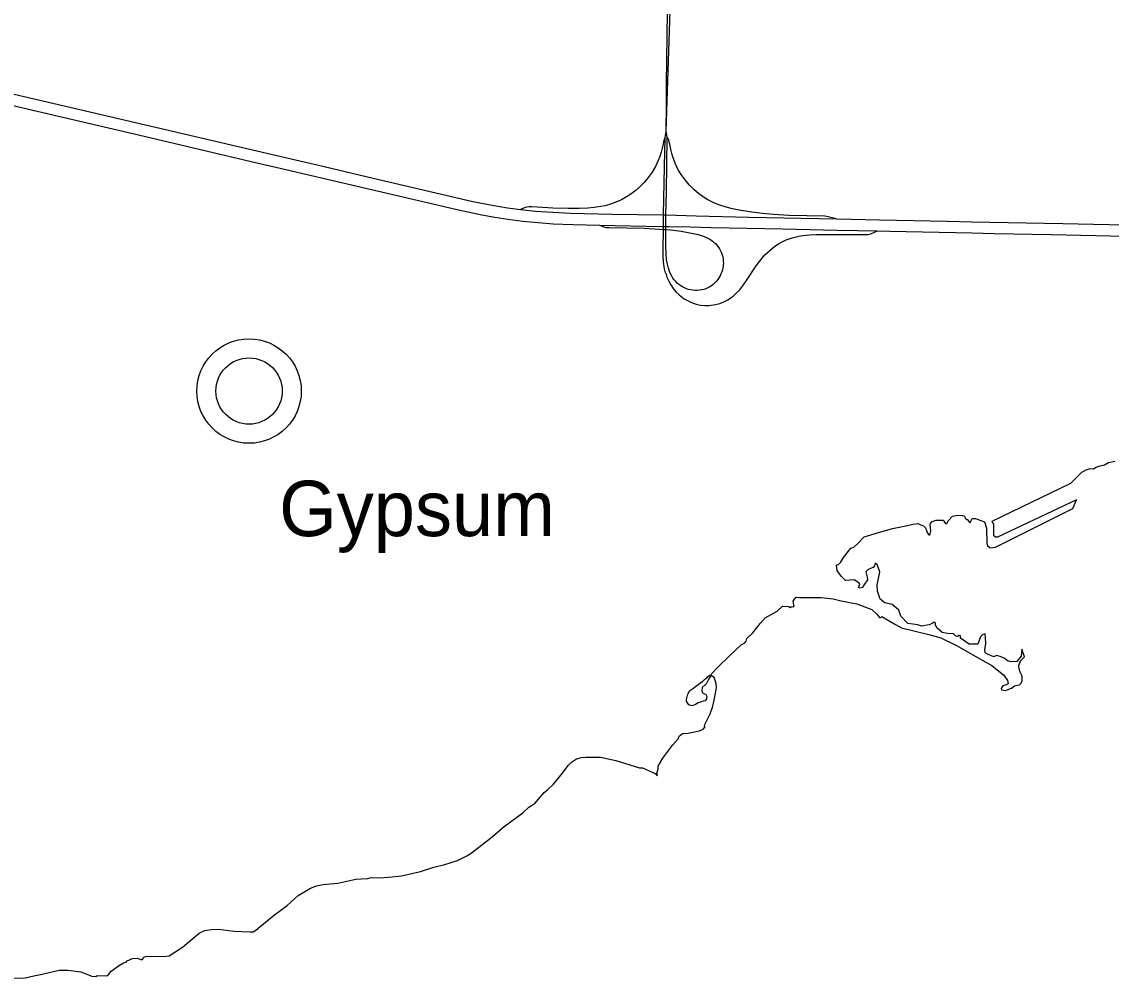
# Model space of a CAD drawing. Extents: x -82 to 873, y 0 to 440.
# Drawn here: x 461.25 to 481.74, y 152.95 to 170.93 of the extents above; entities that cross this region are included whole.
import ezdxf

# ---------------------------------------------------------------- set-up
doc = ezdxf.new("R2010")
doc.units = 0
for name, color, linetype in [('DV_X_Corp_Line', 7, 'Continuous'), ('GM_P_US_Alignment', 7, 'Continuous'), ('GM_X_County', 7, 'Continuous'), ('GM_X_Interchange_Ramps', 7, 'Continuous'), ('GM_X_Interstate_Route', 7, 'Continuous')]:
    doc.layers.add(name, color=color, linetype=linetype)

msp = doc.modelspace()

# ---------------------------------------------------------------- linework, layer by layer
at = {"layer": 'DV_X_Corp_Line'}
for radius in [0.982, 0.623]:
    msp.add_circle((465.521, 163.993), radius, dxfattribs=at)
at = {"layer": 'GM_P_US_Alignment'}
msp.add_lwpolyline([(473.365, 168.87), (473.535, 173.991), (473.96, 183.618), (473.906, 187.531), (484.23, 206.176), (490.737, 211.48), (492.433, 215.185), (491.986, 239.02), (491.811, 239.475), (491.569, 239.636), (491.322, 239.672), (489.332, 239.581), (489.281, 240.625)], dxfattribs=at)
at = {"layer": 'GM_X_County'}
msp.add_lwpolyline([(461, 152.955), (461.307, 152.964), (461.475, 152.998), (461.627, 153.029), (461.95, 153.107), (462.112, 153.108), (462.355, 153.077), (462.56, 152.994), (462.635, 152.99), (462.665, 153.004), (462.848, 153.002), (462.885, 153.03), (462.924, 153.089), (463.082, 153.2), (463.159, 153.245), (463.206, 153.258), (463.228, 153.282), (463.325, 153.326), (463.417, 153.333), (463.48, 153.306), (463.516, 153.309), (463.529, 153.324), (463.537, 153.348), (463.605, 153.372), (463.918, 153.365), (464.019, 153.375), (464.271, 153.537), (464.58, 153.801), (464.686, 153.849), (464.806, 153.868), (464.95, 153.874), (465.231, 153.842), (465.538, 153.824), (465.596, 153.824), (465.645, 153.857), (465.728, 153.925), (465.999, 154.149), (466.237, 154.324), (466.443, 154.507), (466.674, 154.646), (466.79, 154.692), (466.917, 154.714), (467.192, 154.739), (467.528, 154.814), (467.637, 154.824), (467.754, 154.827), (467.816, 154.846), (467.98, 154.842), (468.212, 154.863), (468.39, 154.879), (468.744, 154.958), (468.994, 155.042), (469.204, 155.094), (469.442, 155.166), (469.616, 155.256), (469.698, 155.308), (470.06, 155.589), (470.319, 155.808), (470.669, 156.066), (470.781, 156.17), (470.833, 156.201), (470.886, 156.231), (471.07, 156.445), (471.143, 156.504), (471.244, 156.6), (471.413, 156.812), (471.523, 156.956), (471.584, 157.014), (471.679, 157.077), (471.774, 157.102), (471.855, 157.111), (472.129, 157.11), (472.277, 157.081), (472.418, 157.046), (472.864, 156.911), (472.919, 156.908), (473.158, 156.805), (473.192, 156.768), (473.204, 156.772), (473.188, 156.81), (473.214, 156.885), (473.215, 156.942), (473.306, 157.089), (473.493, 157.345), (473.594, 157.452), (473.61, 157.506), (473.671, 157.555), (473.777, 157.563), (473.992, 157.608), (474.064, 157.638), (474.098, 157.679), (474.087, 157.7), (474.092, 157.727), (474.187, 157.914), (474.235, 158.044), (474.269, 158.183), (474.312, 158.413), (474.308, 158.497), (474.266, 158.609), (474.219, 158.64), (474.196, 158.622), (474.179, 158.603), (474.156, 158.557), (474.122, 158.496), (474.104, 158.475), (474.044, 158.419), (474.034, 158.356), (474.044, 158.328), (474.087, 158.302), (474.114, 158.291), (474.13, 158.253), (474.123, 158.205), (474.099, 158.167), (474.059, 158.165), (474.03, 158.149), (473.97, 158.132), (473.918, 158.1), (473.854, 158.075), (473.794, 158.091), (473.767, 158.13), (473.75, 158.165), (473.745, 158.193), (473.774, 158.292), (473.812, 158.365), (473.859, 158.398), (473.996, 158.501), (474.052, 158.533), (474.09, 158.579), (474.129, 158.599), (474.144, 158.622), (474.19, 158.653), (474.212, 158.661), (474.223, 158.683), (474.33, 158.794), (474.554, 159.015), (474.783, 159.226), (474.837, 159.251), (474.871, 159.289), (474.884, 159.342), (474.995, 159.447), (475.133, 159.626), (475.229, 159.732), (475.453, 159.857), (475.551, 159.949), (475.673, 159.945), (475.696, 159.926), (475.714, 159.936), (475.735, 159.945), (475.757, 159.935), (475.774, 159.948), (475.766, 159.969), (475.753, 160.041), (475.778, 160.081), (475.813, 160.117), (475.872, 160.109), (475.998, 160.109), (476.279, 160.109), (476.506, 160.086), (476.655, 160.049), (476.949, 159.993), (477.234, 159.886), (477.327, 159.797), (477.376, 159.738), (477.406, 159.739), (477.425, 159.755), (477.527, 159.694), (477.681, 159.606), (477.789, 159.541), (478.306, 159.415), (478.529, 159.355), (478.824, 159.209), (479.104, 159.051), (479.267, 158.958), (479.491, 158.832), (479.72, 158.65), (479.785, 158.552), (479.799, 158.487), (479.762, 158.468), (479.697, 158.454), (479.669, 158.403), (479.673, 158.375), (479.748, 158.361), (479.86, 158.407), (479.92, 158.449), (480.014, 158.468), (480.044, 158.5), (480.06, 158.543), (480.06, 158.636), (480.023, 158.71), (480.003, 158.771), (480, 158.832), (480.039, 158.928), (480.105, 158.994), (480.056, 159.14), (480.046, 159.009), (479.962, 158.911), (479.855, 158.902), (479.786, 158.924), (479.734, 158.967), (479.645, 159), (479.58, 159.024), (479.529, 158.995), (479.407, 159.046), (479.365, 159.074), (479.361, 159.13), (479.379, 159.247), (479.375, 159.354), (479.364, 159.427), (479.323, 159.415), (479.281, 159.373), (479.23, 159.233), (479.141, 159.237), (479.062, 159.237), (478.904, 159.345), (478.899, 159.391), (478.879, 159.398), (478.848, 159.377), (478.808, 159.393), (478.773, 159.429), (478.656, 159.433), (478.554, 159.452), (478.46, 159.536), (478.43, 159.591), (478.429, 159.635), (478.405, 159.65), (478.372, 159.626), (478.311, 159.601), (478.171, 159.573), (478.101, 159.601), (477.91, 159.62), (477.779, 159.76), (477.742, 159.872), (477.691, 159.918), (477.615, 159.981), (477.476, 160.012), (477.392, 160.082), (477.341, 160.231), (477.336, 160.343), (477.383, 160.595), (477.336, 160.73), (477.299, 160.758), (477.285, 160.707), (477.257, 160.674), (477.21, 160.655), (477.168, 160.637), (477.122, 160.595), (477.145, 160.497), (477.154, 160.441), (477.084, 160.343), (477.056, 160.297), (477.017, 160.289), (476.986, 160.298), (477.01, 160.361), (476.991, 160.389), (476.902, 160.441), (476.739, 160.431), (476.66, 160.511), (476.581, 160.618), (476.567, 160.725), (476.604, 160.734), (476.646, 160.772), (476.702, 160.865), (476.842, 161.042), (476.893, 161.056), (476.968, 161.126), (477.092, 161.25), (477.343, 161.326), (477.623, 161.411), (477.904, 161.466), (478.003, 161.49), (478.108, 161.504), (478.152, 161.477), (478.174, 161.473), (478.209, 161.459), (478.242, 161.423), (478.281, 161.323), (478.306, 161.289), (478.325, 161.287), (478.334, 161.306), (478.341, 161.361), (478.331, 161.492), (478.371, 161.543), (478.445, 161.565), (478.581, 161.567), (478.589, 161.548), (478.611, 161.509), (478.628, 161.499), (478.653, 161.514), (478.675, 161.559), (478.75, 161.639), (478.854, 161.662), (478.937, 161.652), (478.968, 161.643), (478.981, 161.629), (478.992, 161.601), (479.028, 161.58), (479.064, 161.532), (479.082, 161.515), (479.099, 161.547), (479.123, 161.598), (479.182, 161.598), (479.214, 161.587), (479.351, 161.537), (479.392, 161.414), (479.394, 161.135), (479.412, 161.087), (479.46, 161.045), (479.563, 161.057), (481.014, 161.786), (481.086, 161.948), (479.599, 161.244), (479.557, 161.244), (479.529, 161.274), (479.527, 161.479), (479.497, 161.545), (480.976, 162.259), (481.186, 162.465), (481.267, 162.515), (481.339, 162.534), (481.405, 162.532), (481.452, 162.565), (481.528, 162.586), (481.613, 162.609), (481.683, 162.65), (481.807, 162.676)], dxfattribs=at)
at = {"layer": 'GM_X_Interchange_Ramps'}
for points in [[(473.346, 168.759), (473.321, 168.708), (473.307, 168.642), (473.293, 168.561), (473.273, 168.481), (473.248, 168.402), (473.218, 168.326), (473.164, 168.215), (473.1, 168.109), (473.029, 168.008), (472.95, 167.912), (472.863, 167.825), (472.801, 167.77), (472.703, 167.696), (472.634, 167.65), (472.526, 167.59), (472.451, 167.555), (472.336, 167.511), (472.217, 167.478), (472.137, 167.462), (472.014, 167.444), (471.891, 167.433), (471.727, 167.427), (471.521, 167.425), (471.232, 167.433), (470.944, 167.448), (470.839, 167.457), (470.789, 167.457), (470.716, 167.444), (470.623, 167.406)], [(476.57, 167.228), (476.414, 167.27), (476.348, 167.278), (475.672, 167.296), (475.385, 167.311), (475.18, 167.328), (474.977, 167.353), (474.774, 167.385), (474.613, 167.418), (474.493, 167.448), (474.376, 167.486), (474.262, 167.532), (474.152, 167.587), (474.082, 167.63), (473.982, 167.701), (473.888, 167.781), (473.801, 167.868), (473.722, 167.962), (473.65, 168.062), (473.607, 168.132), (473.568, 168.204), (473.533, 168.279), (473.49, 168.394), (473.471, 168.457), (473.458, 168.512), (473.445, 168.573), (473.432, 168.634), (473.423, 168.673), (473.414, 168.713), (473.403, 168.733), (473.386, 168.763)], [(473.358, 166.207), (473.381, 166.136), (473.413, 166.06), (473.452, 165.988), (473.497, 165.92), (473.55, 165.857), (473.608, 165.8), (473.672, 165.749), (473.706, 165.726), (473.777, 165.686), (473.852, 165.653), (473.93, 165.627), (474.011, 165.61), (474.092, 165.602), (474.174, 165.602), (474.215, 165.605), (474.296, 165.618), (474.375, 165.639), (474.451, 165.67), (474.523, 165.707), (474.591, 165.753), (474.624, 165.777), (474.685, 165.832), (474.742, 165.891), (474.819, 165.987), (474.889, 166.088), (475.046, 166.329), (475.093, 166.396), (475.17, 166.492), (475.224, 166.553), (475.313, 166.638), (475.409, 166.715), (475.478, 166.76), (475.549, 166.8), (475.623, 166.834), (475.738, 166.876), (475.858, 166.905), (475.938, 166.918), (476.061, 166.929), (476.184, 166.934), (476.389, 166.937), (477.165, 166.937), (477.217, 166.947), (477.341, 167.003)]]:
    msp.add_lwpolyline(points, dxfattribs=at)
at = {"layer": 'GM_X_Interstate_Route'}
for points in [[(473.372, 169.382), (473.374, 169.563), (473.375, 169.768), (473.379, 170.22), (473.388, 171.123), (473.402, 171.697), (473.434, 172.476), (473.465, 173.009), (473.518, 173.745), (473.535, 173.991)], [(459.377, 169.977), (465.667, 168.507), (466.933, 168.212), (467.852, 167.995), (469.331, 167.649), (469.732, 167.559), (470.095, 167.487), (470.379, 167.439), (470.623, 167.406), (470.909, 167.377), (471.237, 167.353), (471.566, 167.338), (472.346, 167.321), (473.318, 167.305), (473.361, 167.305), (473.929, 167.285), (474.915, 167.264), (476.57, 167.228), (477.378, 167.211), (478.652, 167.186), (479.11, 167.177), (480.828, 167.141), (481.978, 167.115)], [(459.513, 169.725), (463.548, 168.782), (465.667, 168.286), (466.025, 168.202), (469.46, 167.399), (469.901, 167.305), (470.143, 167.26), (470.385, 167.222), (470.67, 167.187), (470.956, 167.159), (471.242, 167.139), (471.61, 167.125), (472.112, 167.114)], [(473.36, 166.784), (473.361, 167.029), (473.361, 167.088), (473.361, 167.305), (473.37, 167.736), (473.386, 168.763), (473.365, 168.87), (473.372, 169.382)], [(473.358, 166.207), (473.356, 166.214), (473.337, 166.293), (473.318, 166.415), (473.309, 166.538), (473.307, 166.661), (473.314, 167.033), (473.315, 167.089), (473.316, 167.152), (473.318, 167.305), (473.332, 168.217), (473.346, 168.759), (473.365, 168.87)], [(472.112, 167.114), (472.114, 167.114), (473.287, 167.089)], [(472.114, 167.114), (472.209, 167.071), (472.246, 167.065), (472.292, 167.065), (472.952, 167.053), (473.24, 167.038), (473.314, 167.033), (473.361, 167.029), (473.445, 167.021), (473.649, 166.997), (473.81, 166.968), (473.97, 166.934), (474.049, 166.911), (474.125, 166.881), (474.161, 166.862), (474.197, 166.841), (474.231, 166.818), (474.262, 166.792), (474.292, 166.764), (474.32, 166.734), (474.345, 166.702), (474.367, 166.667), (474.387, 166.631), (474.404, 166.594), (474.418, 166.556), (474.429, 166.516), (474.436, 166.476), (474.44, 166.435), (474.441, 166.394), (474.438, 166.353), (474.433, 166.312), (474.424, 166.272), (474.412, 166.233), (474.397, 166.195), (474.379, 166.158), (474.358, 166.122), (474.335, 166.088), (474.31, 166.056), (474.281, 166.026), (474.251, 165.999), (474.218, 165.974), (474.184, 165.952), (474.148, 165.933), (474.11, 165.917), (474.071, 165.904), (474.031, 165.894), (473.991, 165.888), (473.95, 165.885), (473.909, 165.885), (473.868, 165.888), (473.828, 165.895), (473.788, 165.904), (473.749, 165.917), (473.711, 165.933), (473.674, 165.952), (473.639, 165.973), (473.606, 165.997), (473.575, 166.023), (473.545, 166.052), (473.519, 166.082), (473.494, 166.115), (473.472, 166.15), (473.435, 166.223), (473.429, 166.241), (473.408, 166.3), (473.388, 166.379), (473.375, 166.46), (473.364, 166.583), (473.36, 166.706), (473.36, 166.784)], [(473.287, 167.089), (473.315, 167.089), (473.361, 167.088), (473.419, 167.087)], [(473.419, 167.087), (473.815, 167.078)], [(473.815, 167.078), (474.212, 167.07)], [(474.212, 167.07), (475.556, 167.041), (476.583, 167.018), (477.341, 167.003), (477.57, 166.998), (479.113, 166.967), (479.542, 166.957), (480.61, 166.935), (482.008, 166.905)]]:
    msp.add_lwpolyline(points, dxfattribs=at)

# ---------------------------------------------------------------- texts
at = {"layer": 'DV_X_Corp_Line'}
msp.add_text('Gypsum', height=1.0417, rotation=0.005, dxfattribs=at).set_placement((466.086, 161.265))

doc.saveas('drawing.dxf')
